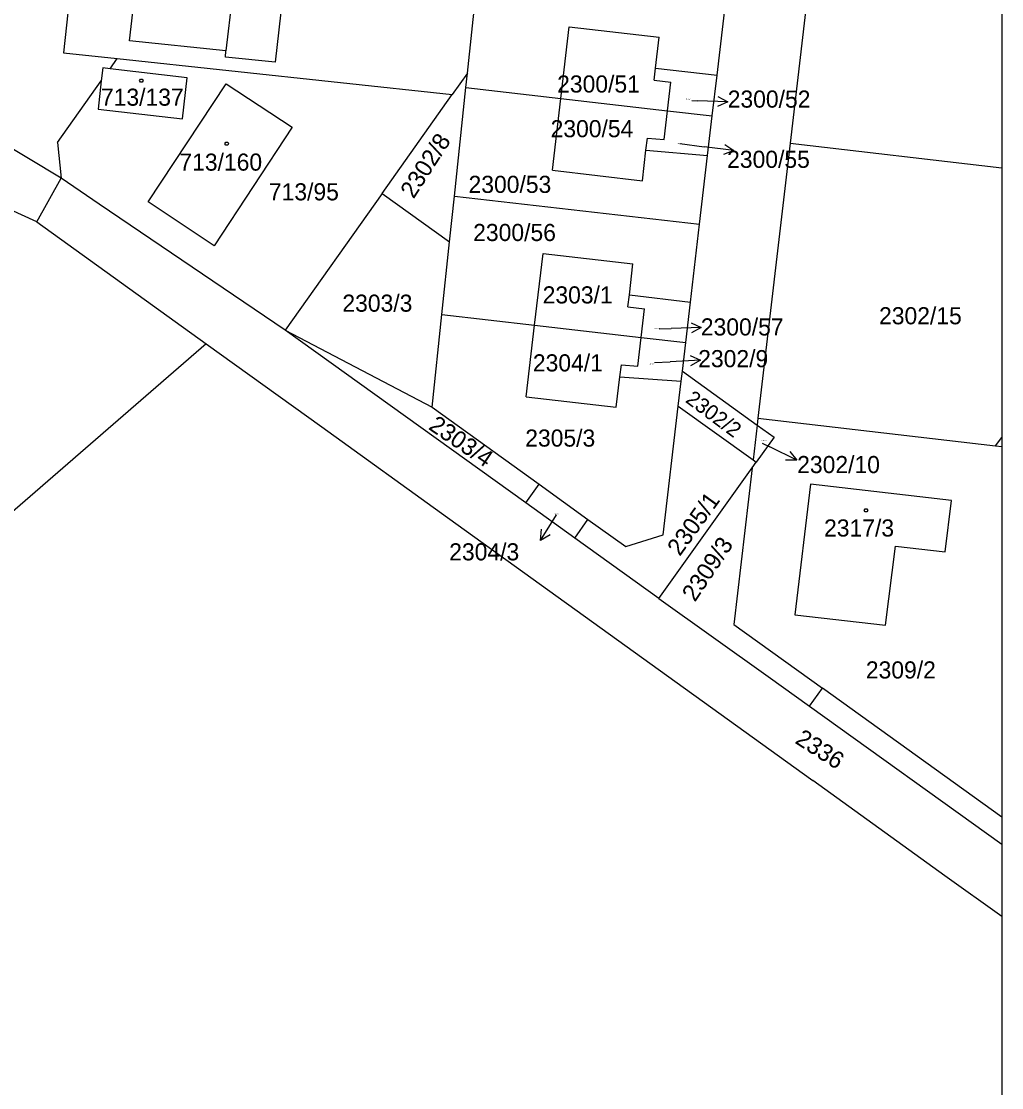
# Model space of a CAD drawing. Extents: x -639590 to -639298, y -1193269 to -1192863.
# Drawn here: x -639395.8 to -639298.4, y -1193117.1 to -1193011.1 of the extents above; entities that cross this region are included whole.
import ezdxf

# ---------------------------------------------------------------- set-up
doc = ezdxf.new("R2010")
doc.units = 0
for name, color, linetype in [('Vrstva 1', 7, 'Continuous'), ('Vrstva 2', 7, 'Continuous'), ('Vrstva 4', 7, 'Continuous'), ('Vrstva 5', 7, 'Continuous'), ('Vrstva 61', 7, 'Continuous'), ('Vrstva 7', 7, 'Continuous')]:
    doc.layers.add(name, color=color, linetype=linetype)

msp = doc.modelspace()

# ---------------------------------------------------------------- linework, layer by layer
at = {"layer": 'Vrstva 1'}
for p, q in [((-639389.63, -1192996.3), (-639391.56, -1193014.27)), ((-639385, -1193013.06), (-639383.4, -1192998.52)), ((-639316.56, -1192998.97), (-639319.4, -1193023.24)), ((-639369.53, -1193006.28), (-639370.56, -1193015.2)), ((-639351.45, -1193016.27), (-639350.36, -1193005.95)), ((-639326.66, -1193016.49), (-639325.76, -1193008.79)), ((-639342.18, -1193018.8), (-639341.36, -1193011.67)), ((-639341.36, -1193011.67), (-639332.41, -1193012.71)), ((-639332.76, -1193015.8), (-639332.41, -1193012.71)), ((-639375.43, -1193014.08), (-639385, -1193013.06)), ((-639391.56, -1193014.27), (-639386.24, -1193014.84)), ((-639386.95, -1193015.84), (-639386.24, -1193014.84)), ((-639386.24, -1193014.84), (-639352.97, -1193018.41)), ((-639375.49, -1193014.71), (-639375.43, -1193014.08)), ((-639370.56, -1193015.2), (-639375.49, -1193014.71)), ((-639387.67, -1193015.75), (-639387.82, -1193017.06)), ((-639386.95, -1193015.84), (-639387.67, -1193015.75)), ((-639379.28, -1193016.74), (-639386.95, -1193015.84)), ((-639332.9, -1193016.99), (-639332.76, -1193015.8)), ((-639332.76, -1193015.8), (-639326.66, -1193016.49)), ((-639392.15, -1193023.17), (-639387.82, -1193017.06)), ((-639387.82, -1193017.06), (-639388.13, -1193019.87)), ((-639379.76, -1193020.83), (-639379.28, -1193016.74)), ((-639351.45, -1193016.27), (-639352.97, -1193018.41)), ((-639351.6, -1193017.71), (-639351.45, -1193016.27)), ((-639332.9, -1193016.99), (-639331.26, -1193017.17)), ((-639331.59, -1193020.02), (-639331.26, -1193017.17)), ((-639327.14, -1193020.54), (-639326.66, -1193016.49)), ((-639383.17, -1193029.06), (-639375.42, -1193017.33)), ((-639375.42, -1193017.33), (-639368.86, -1193021.65)), ((-639352.74, -1193028.49), (-639351.6, -1193017.71)), ((-639351.6, -1193017.71), (-639342.18, -1193018.8)), ((-639359.93, -1193028.23), (-639352.97, -1193018.41)), ((-639342.99, -1193025.93), (-639342.18, -1193018.8)), ((-639342.18, -1193018.8), (-639331.59, -1193020.02)), ((-639388.13, -1193019.87), (-639379.76, -1193020.83)), ((-639331.92, -1193022.87), (-639331.59, -1193020.02)), ((-639331.59, -1193020.02), (-639327.14, -1193020.54)), ((-639391.81, -1193026.72), (-639401.32, -1193021.01)), ((-639327.6, -1193024.45), (-639327.14, -1193020.54)), ((-639368.86, -1193021.65), (-639376.61, -1193033.42)), ((-639392.15, -1193023.17), (-639391.81, -1193026.72)), ((-639333.72, -1193023.92), (-639333.58, -1193022.73)), ((-639333.58, -1193022.73), (-639331.92, -1193022.87)), ((-639319.4, -1193023.24), (-639322.6, -1193050.55)), ((-639319.4, -1193023.24), (-639298.39, -1193025.7)), ((-639334.07, -1193026.98), (-639333.72, -1193023.92)), ((-639333.72, -1193023.92), (-639327.6, -1193024.45)), ((-639328.4, -1193031.29), (-639327.6, -1193024.45)), ((-639394.21, -1193031.06), (-639391.81, -1193026.72)), ((-639388.01, -1193029.3), (-639391.81, -1193026.72)), ((-639342.99, -1193025.93), (-639334.07, -1193026.98)), ((-639359.93, -1193028.23), (-639369.56, -1193041.81)), ((-639359.93, -1193028.23), (-639353.23, -1193033.04)), ((-639353.23, -1193033.04), (-639352.74, -1193028.49)), ((-639352.74, -1193028.49), (-639328.4, -1193031.29)), ((-639394.21, -1193031.06), (-639398.1, -1193029.3)), ((-639369.56, -1193041.81), (-639388.01, -1193029.3)), ((-639376.61, -1193033.42), (-639383.17, -1193029.06)), ((-639394.21, -1193031.06), (-639377.41, -1193043.16)), ((-639329.3, -1193039.04), (-639328.4, -1193031.29)), ((-639353.99, -1193040.25), (-639353.23, -1193033.04)), ((-639344.78, -1193041.31), (-639343.94, -1193034.19)), ((-639343.94, -1193034.19), (-639335.02, -1193035.22)), ((-639335.37, -1193038.3), (-639335.02, -1193035.22)), ((-639335.51, -1193039.49), (-639335.37, -1193038.3)), ((-639335.37, -1193038.3), (-639329.3, -1193039.04)), ((-639329.77, -1193043.04), (-639329.3, -1193039.04)), ((-639354.96, -1193049.46), (-639353.99, -1193040.25)), ((-639353.99, -1193040.25), (-639344.78, -1193041.31)), ((-639335.51, -1193039.49), (-639333.88, -1193039.69)), ((-639334.2, -1193042.53), (-639333.88, -1193039.69)), ((-639345.61, -1193048.44), (-639344.78, -1193041.31)), ((-639344.78, -1193041.31), (-639334.2, -1193042.53)), ((-639369.56, -1193041.81), (-639354.96, -1193049.46)), ((-639345.66, -1193058.97), (-639369.56, -1193041.81)), ((-639334.52, -1193045.38), (-639334.2, -1193042.53)), ((-639334.2, -1193042.53), (-639329.77, -1193043.04)), ((-639377.41, -1193043.16), (-639466.59, -1193120.49)), ((-639377.41, -1193043.16), (-639365.92, -1193051.43)), ((-639330.1, -1193045.89), (-639329.77, -1193043.04)), ((-639336.3, -1193046.46), (-639336.16, -1193045.27)), ((-639336.16, -1193045.27), (-639334.52, -1193045.38)), ((-639336.67, -1193049.45), (-639336.3, -1193046.46)), ((-639336.3, -1193046.46), (-639330.22, -1193046.89)), ((-639330.22, -1193046.89), (-639330.1, -1193045.89)), ((-639330.1, -1193045.89), (-639322.68, -1193051.24)), ((-639330.51, -1193049.36), (-639330.22, -1193046.89)), ((-639345.61, -1193048.44), (-639336.67, -1193049.45)), ((-639354.96, -1193049.46), (-639344.34, -1193057.11)), ((-639332.01, -1193062.15), (-639330.51, -1193049.36)), ((-639330.51, -1193049.36), (-639323.08, -1193054.7)), ((-639322.6, -1193050.55), (-639322.68, -1193051.24)), ((-639322.6, -1193050.55), (-639299, -1193053.31)), ((-639365.92, -1193051.43), (-639353.43, -1193060.43)), ((-639322.68, -1193051.24), (-639323.08, -1193054.7)), ((-639322.68, -1193051.24), (-639321, -1193052.44)), ((-639321, -1193052.44), (-639322.77, -1193054.92)), ((-639299, -1193053.31), (-639298.39, -1193052.46)), ((-639299, -1193053.31), (-639298.39, -1193053.38)), ((-639323.17, -1193055.48), (-639322.77, -1193054.92)), ((-639323.08, -1193054.7), (-639322.77, -1193054.92)), ((-639332.45, -1193068.46), (-639323.17, -1193055.48)), ((-639323.17, -1193055.48), (-639325, -1193071.04)), ((-639345.66, -1193058.97), (-639344.34, -1193057.11)), ((-639344.34, -1193057.11), (-639339.48, -1193060.62)), ((-639317.39, -1193057.1), (-639318.92, -1193070.08)), ((-639303.37, -1193058.74), (-639317.39, -1193057.1)), ((-639340.79, -1193062.47), (-639345.66, -1193058.97)), ((-639303.99, -1193063.83), (-639303.37, -1193058.74)), ((-639353.43, -1193060.43), (-639317.16, -1193086.55)), ((-639340.79, -1193062.47), (-639339.48, -1193060.62)), ((-639339.48, -1193060.62), (-639335.73, -1193063.31)), ((-639332.45, -1193068.46), (-639340.79, -1193062.47)), ((-639335.73, -1193063.31), (-639332.01, -1193062.15)), ((-639309.94, -1193071.13), (-639308.93, -1193063.26)), ((-639308.93, -1193063.26), (-639303.99, -1193063.83)), ((-639332.45, -1193068.46), (-639321.59, -1193076.22)), ((-639318.92, -1193070.08), (-639309.94, -1193071.13)), ((-639325, -1193071.04), (-639316.2, -1193077.38)), ((-639321.59, -1193076.22), (-639317.48, -1193079.17)), ((-639317.48, -1193079.17), (-639316.2, -1193077.38)), ((-639298.39, -1193090.2), (-639316.2, -1193077.38)), ((-639317.48, -1193079.17), (-639298.39, -1193092.86)), ((-639304.03, -1193096), (-639317.16, -1193086.55)), ((-639298.39, -1193100.06), (-639304.03, -1193096))]:
    msp.add_line(p, q, dxfattribs=at)
at = {"layer": 'Vrstva 4'}
msp.add_line((-639374.33, -1193004.66), (-639375.43, -1193014.08), dxfattribs=at)
at = {"layer": 'Vrstva 5'}
for points in [[(-639383.74, -1193016.87), (-639383.65, -1193017.02), (-639383.74, -1193017.17), (-639383.92, -1193017.17), (-639384.01, -1193017.02), (-639383.92, -1193016.87)], [(-639375.26, -1193023.15), (-639375.17, -1193023.3), (-639375.26, -1193023.45), (-639375.44, -1193023.45), (-639375.53, -1193023.3), (-639375.44, -1193023.15)], [(-639311.77, -1193059.57), (-639311.68, -1193059.72), (-639311.77, -1193059.87), (-639311.95, -1193059.87), (-639312.04, -1193059.72), (-639311.95, -1193059.57)]]:
    msp.add_lwpolyline(points, close=True, dxfattribs=at)
at = {"layer": 'Vrstva 61'}
msp.add_lwpolyline([(-639298.39, -1192863.27), (-639298.39, -1193268.77)], dxfattribs=at)
at = {"layer": 'Vrstva 7'}
for p, q in [((-639329.17, -1193019), (-639328.6, -1193019.02)), ((-639325.6, -1193019.13), (-639328.6, -1193019.02)), ((-639330.34, -1193023.28), (-639327.95, -1193023.59)), ((-639324.98, -1193023.98), (-639327.95, -1193023.59)), ((-639328.22, -1193041.55), (-639331.22, -1193041.64)), ((-639332.41, -1193041.67), (-639331.22, -1193041.64)), ((-639332.87, -1193045.04), (-639331.3, -1193044.95)), ((-639328.3, -1193044.79), (-639331.3, -1193044.95)), ((-639322.18, -1193053.03), (-639321.43, -1193053.4)), ((-639318.75, -1193054.74), (-639321.43, -1193053.4)), ((-639344.2, -1193062.7), (-639342.59, -1193060.17))]:
    msp.add_line(p, q, dxfattribs=at)
for points in [[(-639326.58, -1193018.59), (-639325.6, -1193019.13), (-639326.62, -1193019.59)], [(-639325.9, -1193023.36), (-639324.98, -1193023.98), (-639326.03, -1193024.35)], [(-639329.24, -1193041.08), (-639328.22, -1193041.55), (-639329.21, -1193042.08)], [(-639329.33, -1193044.34), (-639328.3, -1193044.79), (-639329.28, -1193045.34)], [(-639319.42, -1193053.85), (-639318.75, -1193054.74), (-639319.86, -1193054.74)], [(-639343.24, -1193062.13), (-639344.2, -1193062.7), (-639344.08, -1193061.59)]]:
    msp.add_lwpolyline(points, dxfattribs=at)

# ---------------------------------------------------------------- texts
at = {"layer": 'Vrstva 2'}
for s, height, p in [('2300/51', 1.7, (-639342.54, -1193018.21)), ('713/137', 1.7, (-639387.85, -1193019.52)), ('2300/52', 0.1, (-639329.75, -1193018.92)), ('2300/54', 1.7, (-639343.19, -1193022.65)), ('2300/55', 0.1, (-639330.66, -1193023.32)), ('713/160', 1.7, (-639380.06, -1193025.97)), ('2300/53', 1.7, (-639351.34, -1193028.18)), ('713/95', 1.7, (-639371.17, -1193028.92)), ('2300/56', 1.7, (-639350.88, -1193032.96)), ('2303/3', 1.7, (-639363.87, -1193039.98)), ('2303/1', 1.7, (-639343.98, -1193039.16)), ('2302/15', 1.7, (-639310.57, -1193041.23)), ('2300/57', 0.1, (-639332.86, -1193041.71)), ('2304/1', 1.7, (-639344.95, -1193045.91)), ('2302/9', 0.1, (-639333.36, -1193045.2)), ('2305/3', 1.7, (-639345.71, -1193053.38)), ('2302/10', 0.1, (-639322.26, -1193052.83)), ('2304/3', 0.1, (-639342.84, -1193060.15)), ('2317/3', 1.7, (-639316.03, -1193062.31)), ('2309/2', 1.7, (-639311.88, -1193076.41))]:
    msp.add_text(s, height=height, dxfattribs=at).set_placement(p)
for s, height, rotation, p in [('2302/8', 1.7, 57.2385, (-639356.8, -1193028.84)), ('2302/2', 1.5, 323.2628, (-639329.89, -1193048.9)), ('2303/4', 1.7, 325.7265, (-639355.41, -1193051.59)), ('2305/1', 1.7, 54.1445, (-639330.36, -1193064.34)), ('2309/3', 1.7, 56.2072, (-639328.85, -1193068.88)), ('2336', 1.7, 327.2735, (-639319.01, -1193082.77))]:
    msp.add_text(s, height=height, rotation=rotation, dxfattribs=at).set_placement(p)
at = {"layer": 'Vrstva 7'}
for s, p in [('2300/52', (-639325.6, -1193019.71)), ('2300/55', (-639325.66, -1193025.69)), ('2300/57', (-639328.27, -1193042.34)), ('2302/9', (-639328.53, -1193045.49)), ('2302/10', (-639318.7, -1193056.01)), ('2304/3', (-639353.26, -1193064.68))]:
    msp.add_text(s, height=1.7, dxfattribs=at).set_placement(p)

doc.saveas('drawing.dxf')
